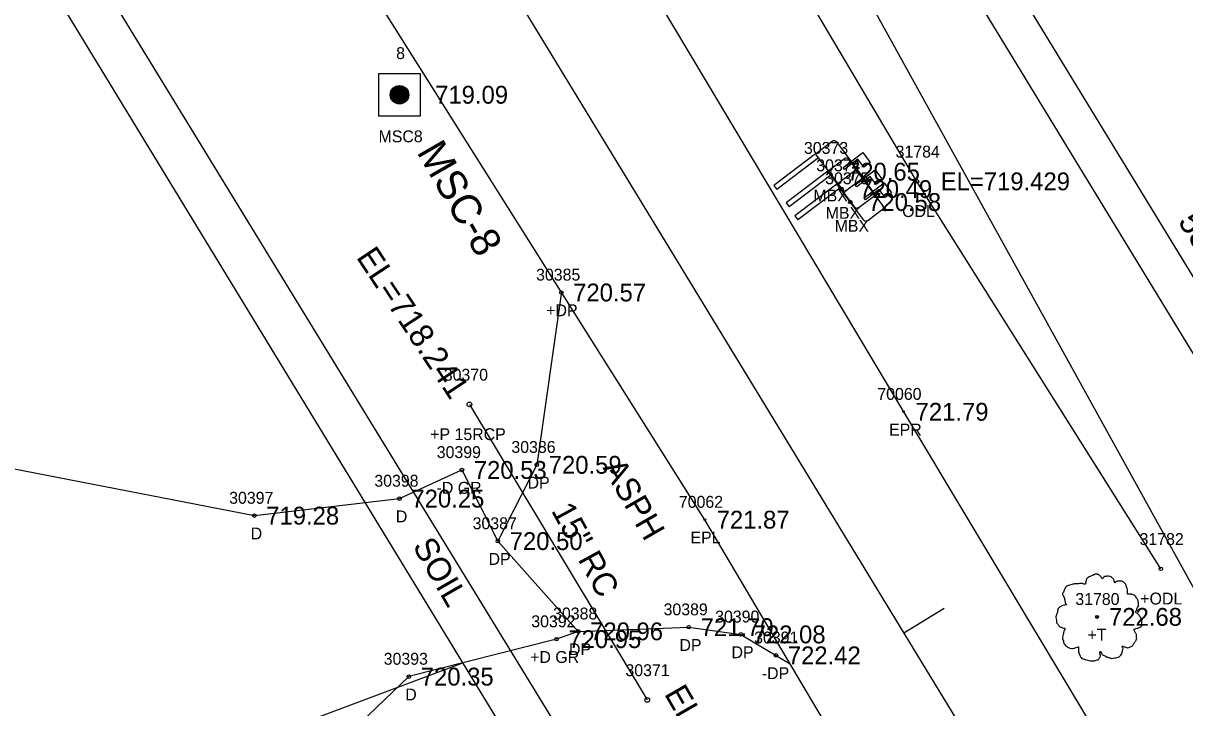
# Model space of a CAD drawing. Extents: x 1375131 to 1378678, y 999028 to 1004053.
# Drawn here: x 1377582.4 to 1377680.1, y 1001174.2 to 1001231.8 of the extents above; entities that cross this region are included whole.
import ezdxf

# ---------------------------------------------------------------- set-up
doc = ezdxf.new("R2010")
doc.units = 0
for name, color, linetype in [('RD_EX_BldgApp', 7, 'Continuous'), ('RD_EX_BldgApp_txCode', 7, 'Continuous'), ('RD_EX_DR_Pipe', 7, 'Continuous'), ('RD_EX_DR_Pipe_txCode', 7, 'Continuous'), ('RD_EX_Driveway', 7, 'Continuous'), ('RD_EX_Driveway_txCode', 7, 'Continuous'), ('RD_EX_DV_Prop', 7, 'Continuous'), ('RD_EX_Fence_Other', 7, 'Continuous'), ('RD_EX_H2O', 7, 'Continuous'), ('RD_EX_H2O_txCode', 7, 'Continuous'), ('RD_EX_Road', 7, 'Continuous'), ('RD_EX_Road_txCode', 7, 'Continuous'), ('RD_EX_RW', 7, 'Continuous'), ('RD_EX_SU_Elec', 7, 'Continuous'), ('RD_EX_TX_BldgApp_ELEV', 7, 'Continuous'), ('RD_EX_TX_Driveway_ELEV', 7, 'Continuous'), ('RD_EX_TX_H2O_ELEV', 7, 'Continuous'), ('RD_EX_TX_Road_ELEV', 7, 'Continuous'), ('RD_EX_TX_VEG_ELEV', 7, 'Continuous'), ('RD_EX_VEG', 7, 'Continuous'), ('RD_EX_VEG_txCode', 7, 'Continuous'), ('RD_HC_Cl', 7, 'Continuous'), ('RD_HC_Data_Tic', 7, 'Continuous'), ('RD_HC_Survey', 7, 'Continuous'), ('RD_HC_Survey_ELEV', 7, 'Continuous'), ('RD_HC_Survey_txCode', 7, 'Continuous'), ('RD_SMD_Locator', 7, 'Continuous'), ('RD_TX_Drainage', 7, 'Continuous'), ('RD_TX_Misc1', 7, 'Continuous'), ('RD_TX_Misc2', 7, 'Continuous'), ('RD_TX_Pipe_ElevEX', 7, 'Continuous')]:
    doc.layers.add(name, color=color, linetype=linetype)

msp = doc.modelspace()

# ---------------------------------------------------------------- linework, layer by layer
at = {"layer": 'RD_EX_BldgApp'}
for p, q in [((1377649.056, 1001220.805), (1377650.451, 1001221.859)), ((1377650.802, 1001221.81), (1377652.931, 1001218.99)), ((1377649.056, 1001220.805), (1377645.536, 1001218.146)), ((1377651.336, 1001217.785), (1377649.056, 1001220.805)), ((1377651.366, 1001219.641), (1377653.037, 1001220.903)), ((1377653.037, 1001220.903), (1377653.657, 1001220.083)), ((1377649.308, 1001220.471), (1377645.788, 1001217.812)), ((1377650.088, 1001219.345), (1377651.483, 1001220.399)), ((1377652.615, 1001220.345), (1377651.481, 1001219.489)), ((1377651.834, 1001220.35), (1377653.963, 1001217.53)), ((1377653.119, 1001219.677), (1377652.615, 1001220.345)), ((1377653.657, 1001220.083), (1377653.119, 1001219.677)), ((1377650.088, 1001219.345), (1377646.568, 1001216.686)), ((1377650.34, 1001219.011), (1377646.82, 1001216.352)), ((1377652.368, 1001216.325), (1377650.088, 1001219.345)), ((1377650.84, 1001218.254), (1377652.235, 1001219.308)), ((1377651.481, 1001219.489), (1377651.366, 1001219.641)), ((1377652.398, 1001218.181), (1377654.069, 1001219.443)), ((1377653.647, 1001218.885), (1377652.513, 1001218.029)), ((1377652.586, 1001219.259), (1377654.715, 1001216.439)), ((1377654.151, 1001218.217), (1377653.647, 1001218.885)), ((1377654.069, 1001219.443), (1377654.689, 1001218.623)), ((1377645.536, 1001218.146), (1377645.788, 1001217.812)), ((1377650.84, 1001218.254), (1377647.32, 1001215.595)), ((1377651.092, 1001217.92), (1377647.572, 1001215.261)), ((1377653.12, 1001215.234), (1377650.84, 1001218.254)), ((1377652.883, 1001218.64), (1377651.686, 1001217.737)), ((1377652.513, 1001218.029), (1377652.398, 1001218.181)), ((1377652.883, 1001218.64), (1377653.082, 1001218.791)), ((1377653.082, 1001218.791), (1377653.233, 1001218.591)), ((1377653.233, 1001218.591), (1377653.133, 1001218.516)), ((1377653.15, 1001217.09), (1377654.821, 1001218.352)), ((1377654.689, 1001218.623), (1377654.151, 1001218.217)), ((1377654.821, 1001218.352), (1377655.441, 1001217.532)), ((1377653.915, 1001217.18), (1377652.718, 1001216.277)), ((1377653.265, 1001216.938), (1377653.15, 1001217.09)), ((1377654.399, 1001217.794), (1377653.265, 1001216.938)), ((1377653.915, 1001217.18), (1377654.114, 1001217.331)), ((1377654.114, 1001217.331), (1377654.265, 1001217.131)), ((1377654.265, 1001217.131), (1377654.165, 1001217.056)), ((1377654.903, 1001217.126), (1377654.399, 1001217.794)), ((1377655.441, 1001217.532), (1377654.903, 1001217.126)), ((1377646.568, 1001216.686), (1377646.82, 1001216.352)), ((1377654.667, 1001216.089), (1377653.47, 1001215.186)), ((1377654.667, 1001216.089), (1377654.866, 1001216.24)), ((1377654.866, 1001216.24), (1377655.017, 1001216.04)), ((1377655.017, 1001216.04), (1377654.917, 1001215.965)), ((1377647.32, 1001215.595), (1377647.572, 1001215.261))]:
    msp.add_line(p, q, dxfattribs=at)
for centre, start, end in [((1377650.602, 1001221.659), 37.06684, 127.06684), ((1377651.634, 1001220.199), 37.06684, 127.06684), ((1377652.386, 1001219.108), 37.06684, 127.06684), ((1377652.732, 1001218.84), 307.06684, 37.06684), ((1377651.536, 1001217.936), 217.06684, 307.06684), ((1377653.764, 1001217.38), 307.06684, 37.06684), ((1377652.568, 1001216.476), 217.06684, 307.06684), ((1377654.516, 1001216.289), 307.06684, 37.06684), ((1377653.32, 1001215.385), 217.06684, 307.06684)]:
    msp.add_arc(centre, 0.25, start, end, dxfattribs=at)
at = {"layer": 'RD_EX_DR_Pipe'}
msp.add_line((1377619.931, 1001199.721), (1377634.891, 1001174.871), dxfattribs=at)
at = {"layer": 'RD_EX_Driveway'}
for points in [[(1377627.664, 1001209.188), (1377625.601, 1001194.646), (1377622.317, 1001188.23), (1377629.086, 1001180.64), (1377638.382, 1001180.988), (1377642.762, 1001180.383), (1377646.919, 1001177.905)], [(1377574.528, 1001195.689), (1377601.833, 1001190.371), (1377614.046, 1001191.806), (1377619.298, 1001194.213), (1377622.317, 1001188.23)], [(1377629.086, 1001180.64), (1377627.252, 1001179.983), (1377614.835, 1001176.832), (1377606.695, 1001169.036), (1377591.108, 1001156.62)]]:
    msp.add_lwpolyline(points, dxfattribs=at)
at = {"layer": 'RD_EX_DV_Prop'}
msp.add_line((1377290.9, 1001055.28), (1377619.369, 1001177.983), dxfattribs=at)
at = {"layer": 'RD_EX_Fence_Other'}
msp.add_lwpolyline([(1377597.866, 1001348.469), (1377630.368, 1001294.188), (1377658.144, 1001247.598), (1377710.368, 1001162.089), (1377732.865, 1001187.522)], dxfattribs=at)
at = {"layer": 'RD_EX_H2O'}
msp.add_lwpolyline([(1377678.108, 1001185.899), (1377657.584, 1001218.485), (1377624.164, 1001274.825), (1377597.907, 1001318.542), (1377572.471, 1001358.752), (1377552.173, 1001397.569), (1377550.102, 1001401.658)], dxfattribs=at)
at = {"layer": 'RD_EX_Road'}
for points in [[(1377899.668, 1000800.294), (1377898.717, 1000801.843), (1377870.308, 1000849.935), (1377847.281, 1000887.888), (1377815.153, 1000940.575), (1377781.512, 1000995.259), (1377748.623, 1001049.208), (1377716.579, 1001099.532), (1377686.671, 1001148.78), (1377656.469, 1001199.107), (1377629.542, 1001244.184), (1377599.886, 1001292.672), (1377570.873, 1001341.428), (1377539.828, 1001392.468), (1377511.01, 1001440.306), (1377480.717, 1001489.998), (1377449.725, 1001541.494), (1377420.899, 1001591.946), (1377390.45, 1001644.414)], [(1377883.752, 1000788.501), (1377882.63, 1000790.224), (1377852.259, 1000839.599), (1377828.464, 1000879.313), (1377796.997, 1000930.663), (1377763.067, 1000986.649), (1377731.866, 1001037.813), (1377700.311, 1001089.979), (1377670.429, 1001138.24), (1377639.732, 1001190.031), (1377611.891, 1001234.227), (1377582.777, 1001282.571), (1377552.217, 1001331.03), (1377522.243, 1001382.346), (1377494.257, 1001430.189), (1377463.172, 1001481.135), (1377433.415, 1001531.286), (1377403.141, 1001580.977), (1377371.36, 1001632.192)]]:
    msp.add_lwpolyline(points, dxfattribs=at)
at = {"layer": 'RD_EX_RW'}
for p, q in [((1377592.75, 1001348.439), (1377983.574, 1000707.362)), ((1377536.397, 1001314.084), (1377927.22, 1000673.007))]:
    msp.add_line(p, q, dxfattribs=at)
at = {"layer": 'RD_EX_SU_Elec'}
msp.add_lwpolyline([(1377525.757, 1001454.692), (1377578.783, 1001251.805), (1377798.03, 1000893.789)], dxfattribs=at)
at = {"layer": 'RD_EX_VEG'}
msp.add_lwpolyline([(1377699.796, 1001150.082), (1377647.337, 1001244.956), (1377619.031, 1001291.876), (1377568.897, 1001377.204)], dxfattribs=at)
for centre, radius in [((1377672.746, 1001181.858), 0.125), ((1377672.74, 1001181.849), 0.00005)]:
    msp.add_circle(centre, radius, dxfattribs=at)
for points in [[(1377672.812, 1001185.442), (1377672.662, 1001185.454), (1377672.5, 1001185.404), (1377672.375, 1001185.354), (1377672.262, 1001185.317), (1377672.15, 1001185.267), (1377672, 1001185.179), (1377671.887, 1001185.079), (1377671.825, 1001184.954), (1377671.8, 1001184.842), (1377671.775, 1001184.704), (1377671.775, 1001184.617), (1377671.712, 1001184.604), (1377671.637, 1001184.617), (1377671.513, 1001184.654), (1377671.388, 1001184.654), (1377671.263, 1001184.654), (1377671.088, 1001184.642), (1377670.913, 1001184.642), (1377670.775, 1001184.617), (1377670.613, 1001184.592), (1377670.426, 1001184.53), (1377670.251, 1001184.467), (1377670.101, 1001184.342), (1377669.976, 1001184.105), (1377669.913, 1001183.93), (1377669.838, 1001183.805), (1377669.913, 1001183.58), (1377670.001, 1001183.405), (1377670.013, 1001183.305), (1377670.051, 1001183.093), (1377670.101, 1001182.98), (1377670.163, 1001182.88), (1377670.126, 1001182.868), (1377669.938, 1001182.843), (1377669.788, 1001182.793), (1377669.576, 1001182.68), (1377669.463, 1001182.568), (1377669.413, 1001182.405), (1377669.401, 1001182.231), (1377669.351, 1001182.131), (1377669.314, 1001181.993), (1377669.301, 1001181.956), (1377669.276, 1001181.793), (1377669.326, 1001181.568), (1377669.339, 1001181.393), (1377669.401, 1001181.281), (1377669.476, 1001181.194), (1377669.563, 1001181.069), (1377669.763, 1001180.956), (1377669.926, 1001180.906), (1377670.026, 1001180.894), (1377669.938, 1001180.644), (1377669.913, 1001180.469), (1377669.851, 1001180.269), (1377669.851, 1001180.231), (1377669.826, 1001179.994), (1377669.901, 1001179.832), (1377669.938, 1001179.644), (1377670.026, 1001179.532), (1377670.163, 1001179.382), (1377670.326, 1001179.269), (1377670.575, 1001179.207), (1377670.775, 1001179.219), (1377671.063, 1001179.307), (1377671.188, 1001179.344), (1377671.175, 1001179.257), (1377671.188, 1001179.069), (1377671.188, 1001178.857), (1377671.263, 1001178.695), (1377671.313, 1001178.557), (1377671.388, 1001178.432), (1377671.55, 1001178.32), (1377671.75, 1001178.282), (1377671.962, 1001178.207), (1377672.187, 1001178.17), (1377672.437, 1001178.157), (1377672.737, 1001178.232), (1377672.874, 1001178.295), (1377672.924, 1001178.382), (1377673.024, 1001178.57), (1377672.999, 1001178.682), (1377673.012, 1001178.982), (1377673.062, 1001178.894), (1377673.149, 1001178.72), (1377673.399, 1001178.57), (1377673.599, 1001178.482), (1377673.837, 1001178.407), (1377673.986, 1001178.37), (1377674.224, 1001178.407), (1377674.411, 1001178.445), (1377674.599, 1001178.507), (1377674.749, 1001178.645), (1377674.836, 1001178.782), (1377674.861, 1001178.919), (1377674.899, 1001179.107), (1377674.924, 1001179.194)], [(1377674.924, 1001179.194), (1377674.886, 1001179.282), (1377674.861, 1001179.407), (1377674.899, 1001179.394), (1377674.986, 1001179.369), (1377675.123, 1001179.307), (1377675.236, 1001179.269), (1377675.398, 1001179.282), (1377675.536, 1001179.332), (1377675.761, 1001179.469), (1377675.898, 1001179.707), (1377676.036, 1001179.907), (1377676.073, 1001180.069), (1377676.048, 1001180.181), (1377676.036, 1001180.431), (1377675.936, 1001180.556), (1377675.911, 1001180.619), (1377675.861, 1001180.819), (1377675.898, 1001180.844), (1377676.036, 1001180.869), (1377676.223, 1001180.931), (1377676.36, 1001180.994), (1377676.473, 1001181.081), (1377676.51, 1001181.194), (1377676.498, 1001181.393), (1377676.523, 1001181.593), (1377676.485, 1001181.668), (1377676.435, 1001181.743), (1377676.398, 1001181.843), (1377676.323, 1001181.918), (1377676.273, 1001181.993), (1377676.223, 1001182.043), (1377676.161, 1001182.118), (1377676.073, 1001182.181), (1377675.998, 1001182.206), (1377675.973, 1001182.281), (1377676.048, 1001182.38), (1377676.073, 1001182.43), (1377676.086, 1001182.543), (1377676.198, 1001182.718), (1377676.223, 1001182.918), (1377676.198, 1001183.13), (1377676.173, 1001183.268), (1377676.098, 1001183.405), (1377675.998, 1001183.53), (1377675.936, 1001183.617), (1377675.848, 1001183.68), (1377675.686, 1001183.742), (1377675.561, 1001183.767), (1377675.386, 1001183.767), (1377675.286, 1001183.792), (1377675.298, 1001183.817), (1377675.298, 1001183.892), (1377675.298, 1001184.03), (1377675.261, 1001184.255), (1377675.186, 1001184.505), (1377675.186, 1001184.517), (1377675.136, 1001184.642), (1377675.024, 1001184.742), (1377674.936, 1001184.792), (1377674.836, 1001184.854), (1377674.711, 1001184.867), (1377674.561, 1001184.867), (1377674.424, 1001184.842), (1377674.324, 1001184.792), (1377674.236, 1001184.729), (1377674.199, 1001184.804), (1377674.149, 1001184.954), (1377674.124, 1001185.029), (1377674.049, 1001185.117), (1377673.937, 1001185.217), (1377673.712, 1001185.279), (1377673.399, 1001185.242), (1377673.249, 1001185.142), (1377673.174, 1001185.054), (1377673.149, 1001185.117), (1377673.049, 1001185.217), (1377672.999, 1001185.304), (1377672.912, 1001185.367), (1377672.837, 1001185.417), (1377672.787, 1001185.442)]]:
    msp.add_spline(points, degree=3, dxfattribs=at)
at = {"layer": 'RD_HC_Cl'}
msp.add_line((1377564.573, 1001331.262), (1377955.397, 1000690.185), dxfattribs=at)
at = {"layer": 'RD_HC_Data_Tic'}
msp.add_line((1377656.472, 1001180.518), (1377659.888, 1001182.6), dxfattribs=at)
at = {"layer": 'RD_HC_Survey'}
for p, q in [((1377613.29, 1001225.588), (1377613.29, 1001225.95)), ((1377613.315, 1001225.505), (1377613.315, 1001226.033)), ((1377613.34, 1001225.444), (1377613.34, 1001226.094)), ((1377613.365, 1001225.394), (1377613.365, 1001226.144)), ((1377613.39, 1001225.352), (1377613.39, 1001226.186)), ((1377613.415, 1001225.315), (1377613.415, 1001226.223)), ((1377613.44, 1001225.282), (1377613.44, 1001226.256)), ((1377613.465, 1001225.253), (1377613.465, 1001226.285)), ((1377613.49, 1001225.226), (1377613.49, 1001226.312)), ((1377613.515, 1001225.201), (1377613.515, 1001226.337)), ((1377613.54, 1001225.179), (1377613.54, 1001226.359)), ((1377613.565, 1001225.158), (1377613.565, 1001226.38)), ((1377613.59, 1001225.139), (1377613.59, 1001226.399)), ((1377613.615, 1001225.122), (1377613.615, 1001226.416)), ((1377613.64, 1001225.106), (1377613.64, 1001226.432)), ((1377613.665, 1001225.091), (1377613.665, 1001226.447)), ((1377613.69, 1001225.078), (1377613.69, 1001226.46)), ((1377613.715, 1001225.066), (1377613.715, 1001226.472)), ((1377613.74, 1001225.054), (1377613.74, 1001226.484)), ((1377613.765, 1001225.044), (1377613.765, 1001226.494)), ((1377613.79, 1001225.035), (1377613.79, 1001226.503)), ((1377613.815, 1001225.027), (1377613.815, 1001226.511)), ((1377613.84, 1001225.019), (1377613.84, 1001226.519)), ((1377613.865, 1001225.013), (1377613.865, 1001226.525)), ((1377613.89, 1001225.008), (1377613.89, 1001226.53)), ((1377613.915, 1001225.003), (1377613.915, 1001226.535)), ((1377613.94, 1001224.999), (1377613.94, 1001226.539)), ((1377613.965, 1001224.996), (1377613.965, 1001226.542)), ((1377613.99, 1001224.994), (1377613.99, 1001226.544)), ((1377614.015, 1001224.992), (1377614.015, 1001226.546)), ((1377614.04, 1001224.992), (1377614.04, 1001226.546)), ((1377614.065, 1001224.992), (1377614.065, 1001226.546)), ((1377614.09, 1001224.993), (1377614.09, 1001226.545)), ((1377614.115, 1001224.995), (1377614.115, 1001226.543)), ((1377614.14, 1001224.997), (1377614.14, 1001226.541)), ((1377614.165, 1001225.001), (1377614.165, 1001226.537)), ((1377614.19, 1001225.005), (1377614.19, 1001226.533)), ((1377614.215, 1001225.01), (1377614.215, 1001226.528)), ((1377614.24, 1001225.016), (1377614.24, 1001226.522)), ((1377614.265, 1001225.023), (1377614.265, 1001226.515)), ((1377614.29, 1001225.031), (1377614.29, 1001226.507)), ((1377614.315, 1001225.04), (1377614.315, 1001226.498)), ((1377614.34, 1001225.049), (1377614.34, 1001226.489)), ((1377614.365, 1001225.06), (1377614.365, 1001226.478)), ((1377614.39, 1001225.072), (1377614.39, 1001226.466)), ((1377614.415, 1001225.085), (1377614.415, 1001226.453)), ((1377614.44, 1001225.099), (1377614.44, 1001226.439)), ((1377614.465, 1001225.114), (1377614.465, 1001226.424)), ((1377614.49, 1001225.131), (1377614.49, 1001226.407)), ((1377614.515, 1001225.149), (1377614.515, 1001226.389)), ((1377614.54, 1001225.169), (1377614.54, 1001226.369)), ((1377614.565, 1001225.19), (1377614.565, 1001226.348)), ((1377614.59, 1001225.214), (1377614.59, 1001226.324)), ((1377614.615, 1001225.24), (1377614.615, 1001226.298)), ((1377614.64, 1001225.268), (1377614.64, 1001226.27)), ((1377614.665, 1001225.299), (1377614.665, 1001226.239)), ((1377614.69, 1001225.334), (1377614.69, 1001226.204)), ((1377614.715, 1001225.373), (1377614.715, 1001226.165)), ((1377614.74, 1001225.419), (1377614.74, 1001226.119)), ((1377614.765, 1001225.474), (1377614.765, 1001226.064)), ((1377614.79, 1001225.544), (1377614.79, 1001225.994)), ((1377614.815, 1001225.656), (1377614.815, 1001225.882))]:
    msp.add_line(p, q, dxfattribs=at)
msp.add_lwpolyline([(1377615.814, 1001227.537), (1377612.278, 1001227.537), (1377612.278, 1001224.001), (1377615.814, 1001224.001)], close=True, dxfattribs=at)
msp.add_circle((1377614.046, 1001225.769), 0.777, dxfattribs=at)
at = {"layer": 'RD_SMD_Locator'}
for centre, radius in [((1377614.046, 1001225.769), 0.075), ((1377650.196, 1001219.295), 0.15), ((1377651.228, 1001217.835), 0.15), ((1377657.584, 1001218.485), 0.15), ((1377651.98, 1001216.744), 0.15), ((1377627.657, 1001209.139), 0.15), ((1377619.931, 1001199.721), 0.2), ((1377656.469, 1001199.107), 0.075), ((1377625.601, 1001194.646), 0.15), ((1377619.298, 1001194.213), 0.15), ((1377614.046, 1001191.806), 0.15), ((1377601.833, 1001190.371), 0.15), ((1377639.732, 1001190.031), 0.075), ((1377622.317, 1001188.23), 0.15), ((1377678.108, 1001185.899), 0.15), ((1377672.746, 1001181.858), 0.075), ((1377629.086, 1001180.64), 0.15), ((1377638.382, 1001180.988), 0.15), ((1377627.252, 1001179.983), 0.15), ((1377642.762, 1001180.383), 0.15), ((1377645.721, 1001178.619), 0.15), ((1377614.835, 1001176.832), 0.15), ((1377634.891, 1001174.871), 0.2)]:
    msp.add_circle(centre, radius, dxfattribs=at)

# ---------------------------------------------------------------- texts
at = {"layer": 'RD_EX_BldgApp_txCode'}
for s, p in [('30373', (1377648.078, 1001220.795)), ('30374', (1377649.11, 1001219.335)), ('30375', (1377649.862, 1001218.244)), ('MBX', (1377648.873, 1001216.795)), ('MBX', (1377649.905, 1001215.335)), ('MBX', (1377650.657, 1001214.244))]:
    msp.add_text(s, height=1, dxfattribs=at).set_placement(p)
at = {"layer": 'RD_EX_DR_Pipe_txCode'}
for s, p in [('30370', (1377617.774, 1001201.721)), ('+P 15RCP', (1377616.632, 1001196.721)), ('30371', (1377633.056, 1001176.871))]:
    msp.add_text(s, height=1, dxfattribs=at).set_placement(p)
at = {"layer": 'RD_EX_Driveway_txCode'}
for s, p in [('30385', (1377625.539, 1001210.139)), ('+DP', (1377626.389, 1001207.139)), ('30386', (1377623.459, 1001195.646)), ('30399', (1377617.18, 1001195.213)), ('30398', (1377611.928, 1001192.806)), ('DP', (1377624.821, 1001192.646)), ('-D GR', (1377617.164, 1001192.213)), ('30397', (1377599.715, 1001191.371)), ('D', (1377613.739, 1001189.806)), ('30387', (1377620.199, 1001189.23)), ('D', (1377601.526, 1001188.371)), ('DP', (1377621.537, 1001186.23)), ('30388', (1377626.968, 1001181.64)), ('30389', (1377636.264, 1001181.988)), ('30392', (1377625.134, 1001180.983)), ('30390', (1377640.605, 1001181.383)), ('DP', (1377637.602, 1001178.988)), ('30391', (1377643.886, 1001179.619)), ('30393', (1377612.717, 1001177.832)), ('+D GR', (1377625.039, 1001177.983)), ('DP', (1377628.306, 1001178.64)), ('DP', (1377641.982, 1001178.383)), ('-DP', (1377644.532, 1001176.619)), ('D', (1377614.528, 1001174.832))]:
    msp.add_text(s, height=1, dxfattribs=at).set_placement(p)
at = {"layer": 'RD_EX_H2O_txCode'}
for s, p in [('31784', (1377655.789, 1001220.485)), ('ODL', (1377656.34, 1001215.485)), ('31782', (1377676.313, 1001187.899)), ('+ODL', (1377676.376, 1001182.899))]:
    msp.add_text(s, height=1, dxfattribs=at).set_placement(p)
at = {"layer": 'RD_EX_Road_txCode'}
for s, p in [('70060', (1377654.249, 1001200.107)), ('EPR', (1377655.241, 1001197.107)), ('70062', (1377637.551, 1001191.031)), ('EPL', (1377638.527, 1001188.031))]:
    msp.add_text(s, height=1, dxfattribs=at).set_placement(p)
at = {"layer": 'RD_EX_TX_BldgApp_ELEV'}
for s, p in [('720.65', (1377651.696, 1001218.545)), ('720.49', (1377652.728, 1001217.085)), ('720.58', (1377653.48, 1001215.994))]:
    msp.add_text(s, height=1.5, dxfattribs=at).set_placement(p)
at = {"layer": 'RD_EX_TX_Driveway_ELEV'}
for s, p in [('720.57', (1377628.657, 1001208.389)), ('720.59', (1377626.601, 1001193.896)), ('720.53', (1377620.298, 1001193.463)), ('720.25', (1377615.046, 1001191.056)), ('719.28', (1377602.833, 1001189.621)), ('720.50', (1377623.317, 1001187.48)), ('721.70', (1377639.382, 1001180.238)), ('720.95', (1377628.252, 1001179.233)), ('720.96', (1377630.086, 1001179.89)), ('722.08', (1377643.762, 1001179.633)), ('722.42', (1377646.721, 1001177.869)), ('720.35', (1377615.835, 1001176.082))]:
    msp.add_text(s, height=1.5, dxfattribs=at).set_placement(p)
at = {"layer": 'RD_EX_TX_H2O_ELEV'}
msp.add_text('EL=719.429', height=1.5, dxfattribs=at).set_placement((1377659.584, 1001217.735))
at = {"layer": 'RD_EX_TX_Road_ELEV'}
for s, p in [('721.79', (1377657.469, 1001198.357)), ('721.87', (1377640.732, 1001189.281))]:
    msp.add_text(s, height=1.5, dxfattribs=at).set_placement(p)
at = {"layer": 'RD_EX_TX_VEG_ELEV'}
msp.add_text('722.68', height=1.5, dxfattribs=at).set_placement((1377673.746, 1001181.108))
at = {"layer": 'RD_EX_VEG_txCode'}
for s, p in [('31780', (1377670.911, 1001182.858)), ('+T', (1377671.935, 1001179.858))]:
    msp.add_text(s, height=1, dxfattribs=at).set_placement(p)
at = {"layer": 'RD_HC_Survey_ELEV'}
msp.add_text('719.09', height=1.5, dxfattribs=at).set_placement((1377617.046, 1001225.019))
at = {"layer": 'RD_HC_Survey_txCode'}
for s, p in [('8', (1377613.763, 1001228.769)), ('MSC8', (1377612.282, 1001221.769))]:
    msp.add_text(s, height=1, dxfattribs=at).set_placement(p)
at = {"layer": 'RD_TX_Drainage'}
msp.add_text('15" RC', height=2, rotation=298.65103, dxfattribs=at).set_placement((1377626.774, 1001190.801))
at = {"layer": 'RD_TX_Misc1'}
msp.add_text('MSC-8', height=2.5, rotation=299.98856, dxfattribs=at).set_placement((1377615.451, 1001220.965))
at = {"layer": 'RD_TX_Misc2'}
for s, rotation, p in [('5SBW', 302.35863, (1377679.497, 1001215.11)), ('ASPH', 300.0183, (1377631.102, 1001194.411)), ('SOIL', 300.0183, (1377615.104, 1001187.805))]:
    msp.add_text(s, height=2, rotation=rotation, dxfattribs=at).set_placement(p)
at = {"layer": 'RD_TX_Pipe_ElevEX'}
for s, rotation, p in [('EL=718.241', 303.46267, (1377610.356, 1001212.11)), ('EL=719.337', 299.9021, (1377636.283, 1001175.392))]:
    msp.add_text(s, height=2, rotation=rotation, dxfattribs=at).set_placement(p)

doc.saveas('drawing.dxf')
